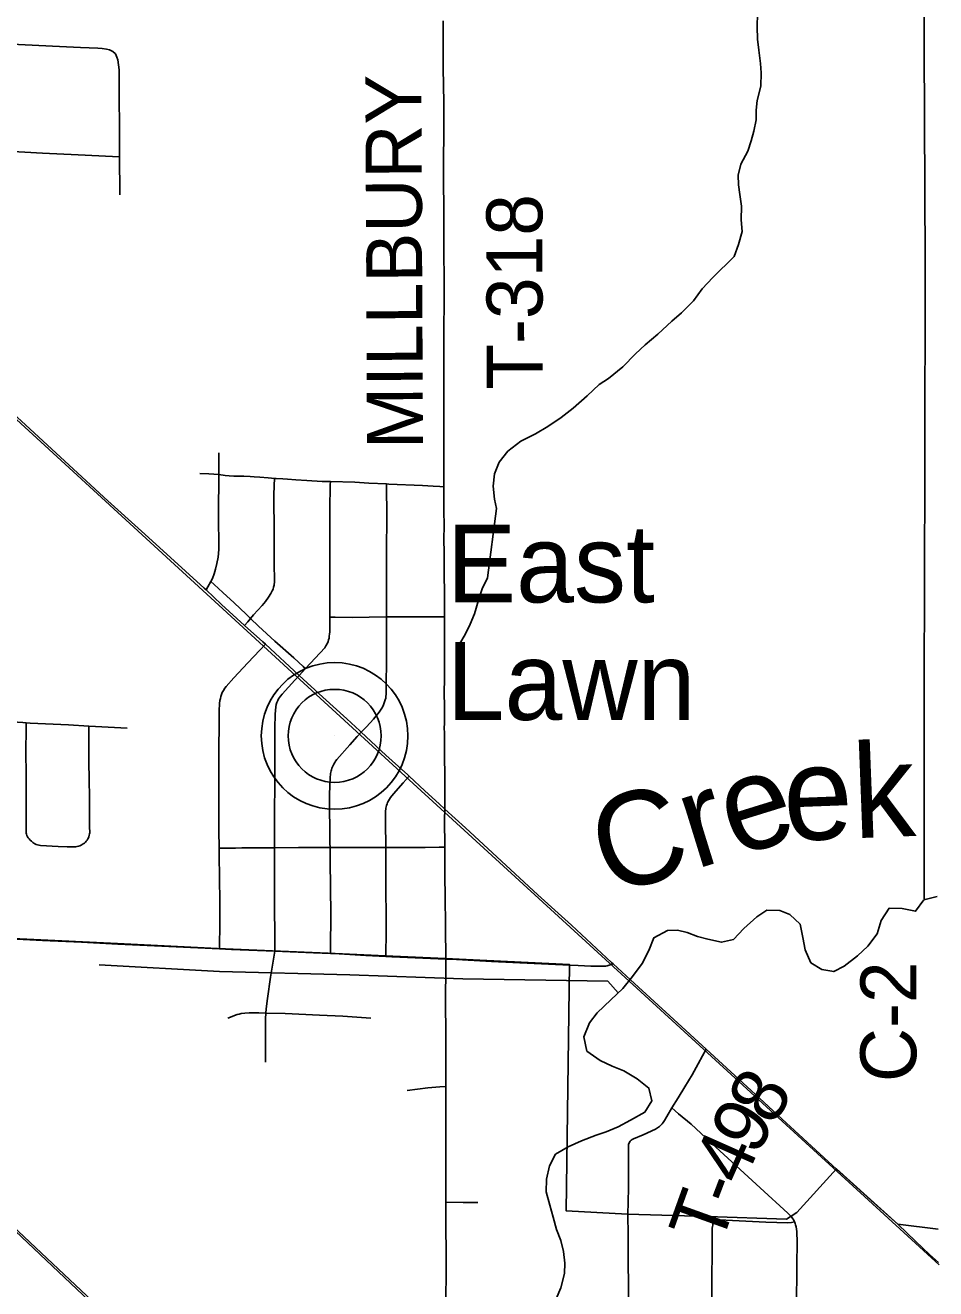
# Model space of a CAD drawing. Extents: x 0 to 34, y 0 to 22.
# Drawn here: x 3.778 to 4.702, y 18.031 to 19.313 of the extents above; entities that cross this region are included whole.
import ezdxf

# ---------------------------------------------------------------- set-up
doc = ezdxf.new("R2010")
doc.units = 0
for name, color, linetype in [('GM_X_City_Street', 7, 'Continuous'), ('GM_X_Corporation', 7, 'Continuous'), ('GM_X_County_Road_Text', 7, 'Continuous'), ('GM_X_Minor_River', 7, 'Continuous'), ('GM_X_Minor_River_Text', 7, 'Continuous'), ('GM_X_Rail_Line', 7, 'Continuous'), ('GM_X_State_Route', 7, 'Continuous'), ('GM_X_Township_Road', 7, 'Continuous'), ('GM_X_Township_Road_Text', 7, 'Continuous'), ('GM_X_Unincorporated', 7, 'Continuous'), ('GM_X_Unincorporated_Location', 7, 'Continuous'), ('GM_X_Unincorporated_Text', 7, 'Continuous')]:
    doc.layers.add(name, color=color, linetype=linetype)

msp = doc.modelspace()

# ---------------------------------------------------------------- linework, layer by layer
at = {"layer": 'GM_X_City_Street'}
for points in [[(4.0224, 18.261), (4.0222, 18.2901), (4.0224, 18.305), (4.0227, 18.3109), (4.023, 18.3154), (4.0242, 18.3259), (4.0274, 18.3474), (4.0316, 18.3737)], [(3.9839, 18.3059), (3.9934, 18.3094), (3.9955, 18.31), (3.9976, 18.3104), (4.0013, 18.3109), (4.0056, 18.3111), (4.0156, 18.3111), (4.0227, 18.3109), (4.0423, 18.3104), (4.0771, 18.3087), (4.1007, 18.3077), (4.129, 18.3058)], [(4.166, 18.2325), (4.1869, 18.235), (4.195, 18.2359), (4.1993, 18.2362), (4.2052, 18.2366)], [(4.2047, 17.9902), (4.2056, 18.043), (4.2054, 18.1191)], [(4.2054, 18.1191), (4.223, 18.1189), (4.2378, 18.1187)], [(4.4761, 17.8564), (4.4762, 17.8627), (4.476, 17.8834), (4.4758, 17.9298), (4.4758, 17.9786), (4.4753, 18.0223), (4.4755, 18.0881), (4.4756, 18.0908), (4.4757, 18.0928), (4.4758, 18.0944), (4.4761, 18.0959), (4.4764, 18.0969), (4.4769, 18.0978), (4.4774, 18.0985), (4.4778, 18.099), (4.4782, 18.0994)], [(4.4782, 18.0994), (4.4788, 18.0998), (4.4797, 18.1003), (4.4808, 18.1007), (4.4817, 18.101), (4.4827, 18.1011), (4.53, 18.0988), (4.5525, 18.0981), (4.556, 18.0985), (4.5592, 18.0993)], [(4.5613, 17.853), (4.5613, 17.859), (4.5615, 17.894), (4.5613, 17.9791), (4.5612, 18.0155), (4.5616, 18.0522), (4.5617, 18.0818), (4.5616, 18.0855), (4.5615, 18.0892), (4.5611, 18.0916), (4.5607, 18.0941), (4.5603, 18.0961), (4.5599, 18.0976), (4.5592, 18.0993)]]:
    msp.add_lwpolyline(points, dxfattribs=at)
at = {"layer": 'GM_X_Corporation'}
msp.add_lwpolyline([(3.7011, 17.8859), (3.7017, 18.3895), (3.872, 18.3816), (3.9736, 18.3766), (4.0293, 18.3741), (4.0857, 18.3716), (4.1442, 18.3689), (4.2049, 18.3663), (4.3308, 18.3601), (4.3274, 18.1103), (4.3898, 18.1068), (4.471, 18.1046), (4.551, 18.1019), (4.5614, 18.1087), (4.6016, 18.153), (4.664, 18.0969), (4.7049, 18.0918)], dxfattribs=at)
at = {"layer": 'GM_X_Minor_River'}
for points in [[(4.6905, 19.9543), (4.6896, 19.826), (4.6912, 19.6693), (4.691, 19.4633), (4.6915, 19.4242), (4.6909, 19.291), (4.6916, 19.0736), (4.6913, 18.8626), (4.6909, 18.6418), (4.6909, 18.427)], [(4.5218, 19.3389), (4.5214, 19.3116), (4.5216, 19.2991), (4.5229, 19.2877), (4.5246, 19.2744), (4.5252, 19.2649), (4.525, 19.2512), (4.5213, 19.2368), (4.5201, 19.227), (4.5203, 19.2171), (4.5178, 19.2058), (4.515, 19.196), (4.5118, 19.1854), (4.5048, 19.1722), (4.502, 19.1609), (4.5022, 19.1514), (4.5036, 19.1415), (4.5053, 19.1297), (4.5051, 19.1157), (4.506, 19.1039), (4.5024, 19.0907), (4.498, 19.0786), (4.4761, 19.0573), (4.4654, 19.0458), (4.4565, 19.0334), (4.4445, 19.0214), (4.4346, 19.0129), (4.4204, 18.9998), (4.4077, 18.989), (4.3977, 18.9797), (4.385, 18.9666), (4.3705, 18.9547), (4.3609, 18.9488), (4.3486, 18.9372), (4.3344, 18.9245), (4.3222, 18.9153), (4.3088, 18.906), (4.2962, 18.8986), (4.2813, 18.8912), (4.2683, 18.8812), (4.2594, 18.87), (4.2547, 18.8579), (4.2534, 18.8454), (4.2547, 18.8325), (4.2568, 18.823), (4.2474, 18.7525), (4.2423, 18.7412), (4.2383, 18.7299), (4.2343, 18.7159), (4.23, 18.7054), (4.2253, 18.6956), (4.2191, 18.6851)], [(4.7038, 18.4291), (4.6905, 18.4259), (4.682, 18.4142), (4.6684, 18.4171), (4.6552, 18.4173), (4.6471, 18.4049), (4.6431, 18.3913), (4.6334, 18.379), (4.623, 18.3689), (4.6096, 18.3585), (4.599, 18.353), (4.5869, 18.3551), (4.5756, 18.3621), (4.5698, 18.3751), (4.5677, 18.3876), (4.5649, 18.401), (4.5545, 18.411), (4.5443, 18.4149), (4.5311, 18.4152), (4.5208, 18.4085), (4.5077, 18.3969), (4.4973, 18.3857), (4.4852, 18.3829), (4.4712, 18.3861), (4.4607, 18.3886), (4.4501, 18.3926), (4.4403, 18.395), (4.4301, 18.3948), (4.4164, 18.3874), (4.4113, 18.3746), (4.4046, 18.3614), (4.3946, 18.3479), (4.3849, 18.3359), (4.3727, 18.3244), (4.3588, 18.3113), (4.3511, 18.3012), (4.3452, 18.2868), (4.3484, 18.2724), (4.3619, 18.2627), (4.3742, 18.2572), (4.3859, 18.2524), (4.3994, 18.2442), (4.4114, 18.2349), (4.4142, 18.222), (4.4072, 18.2103), (4.3927, 18.2022), (4.3801, 18.1956), (4.3679, 18.1905), (4.358, 18.1872), (4.3428, 18.1814), (4.3295, 18.1751), (4.3165, 18.1678), (4.3106, 18.1561), (4.3074, 18.1425), (4.3072, 18.1296), (4.3108, 18.1162), (4.3143, 18.104), (4.3176, 18.0915), (4.3219, 18.0804), (4.3248, 18.069), (4.3261, 18.0572), (4.3256, 18.0469), (4.3219, 18.0322), (4.3172, 18.0209)], [(4.3802, 18.3315), (4.3696, 18.3434), (4.2224, 18.3457), (4.1079, 18.3499), (3.9755, 18.3531), (3.8534, 18.36)]]:
    msp.add_lwpolyline(points, dxfattribs=at)
at = {"layer": 'GM_X_Rail_Line'}
for points in [[(2.1, 20.4531), (2.5585, 20.0312), (3.0884, 19.5461), (3.6994, 18.9771), (4.1763, 18.5403), (4.7059, 18.0556)], [(2.1, 19.6439), (2.1012, 19.6428), (2.4982, 19.2743), (2.9696, 18.8359), (3.3468, 18.4857), (3.702, 18.1547), (3.9505, 17.921), (4.0191, 17.8627), (4.0357, 17.8486), (4.0945, 17.8067), (4.1695, 17.7587), (4.2566, 17.7148), (4.3444, 17.681), (4.4559, 17.6499), (4.5498, 17.6344), (4.6383, 17.6263), (4.7029, 17.6237), (4.7039, 17.6237)], [(2.1, 19.64), (2.4967, 19.2714), (2.9674, 18.8343), (3.3458, 18.483), (3.6997, 18.1544), (3.9489, 17.9193), (4.0176, 17.861), (4.0342, 17.8468), (4.0931, 17.8048), (4.1683, 17.7567), (4.2556, 17.7127), (4.3436, 17.6788), (4.4554, 17.6477), (4.5495, 17.6321), (4.6381, 17.624), (4.7029, 17.6214), (4.7039, 17.6214)]]:
    msp.add_lwpolyline(points, dxfattribs=at)
at = {"layer": 'GM_X_State_Route'}
for points in [[(3.9619, 18.7402), (3.9599, 18.7422), (3.9221, 18.7764), (3.8965, 18.8), (3.8623, 18.8308), (3.8055, 18.8829), (3.7786, 18.9078), (3.758, 18.9268), (3.7357, 18.9476), (3.7211, 18.9611), (3.7048, 18.9762), (3.7015, 18.9792)], [(3.7015, 18.9792), (3.7048, 18.9762), (3.7211, 18.9611), (3.7357, 18.9476), (3.758, 18.9268), (3.7786, 18.9078), (3.8055, 18.8829), (3.8623, 18.8308), (3.8965, 18.8), (3.9221, 18.7764), (3.9599, 18.7422), (3.9619, 18.7402)], [(4.6019, 18.1525), (4.5466, 18.2034), (4.5237, 18.2245), (4.4694, 18.2742), (4.4365, 18.3043), (4.3926, 18.3447), (4.375, 18.3609), (4.3734, 18.3624), (4.3328, 18.4001), (4.3194, 18.4122), (4.2986, 18.4309), (4.2617, 18.4652), (4.2251, 18.499), (4.2041, 18.5179), (4.1985, 18.5231), (4.1839, 18.5366), (4.1681, 18.5513), (4.1666, 18.5527), (4.1444, 18.5727), (4.1194, 18.5958), (4.1179, 18.5972), (4.1047, 18.6094), (4.0804, 18.6316), (4.0565, 18.6535), (4.0221, 18.6852), (4.0195, 18.6876), (4.0009, 18.7042), (3.9775, 18.7255), (3.9619, 18.7402)], [(3.9619, 18.7402), (3.9775, 18.7255), (4.0009, 18.7042), (4.0195, 18.6876), (4.0221, 18.6852), (4.0565, 18.6535), (4.0804, 18.6316), (4.1047, 18.6094), (4.1179, 18.5972), (4.1194, 18.5958), (4.1444, 18.5727), (4.1666, 18.5527), (4.1681, 18.5513), (4.1839, 18.5366), (4.1985, 18.5231), (4.2041, 18.5179), (4.2251, 18.499), (4.2617, 18.4652), (4.2986, 18.4309), (4.3194, 18.4122), (4.3328, 18.4001), (4.3734, 18.3624), (4.375, 18.3609), (4.3926, 18.3447), (4.4365, 18.3043), (4.4694, 18.2742), (4.5237, 18.2245), (4.5466, 18.2034), (4.6019, 18.1525)], [(4.6642, 18.0963), (4.6399, 18.1181), (4.6113, 18.1442), (4.6019, 18.1525)], [(4.6019, 18.1525), (4.6113, 18.1442), (4.6399, 18.1181), (4.6642, 18.0963)], [(4.7052, 18.0579), (4.6963, 18.0659), (4.6818, 18.0796), (4.6642, 18.0963)], [(4.6642, 18.0963), (4.6818, 18.0796), (4.6963, 18.0659), (4.7052, 18.0579)]]:
    msp.add_lwpolyline(points, dxfattribs=at)
at = {"layer": 'GM_X_Township_Road'}
msp.add_line((4.0565, 18.6535), (4.0629, 18.6605), dxfattribs=at)
for points in [[(4.2033, 18.845), (4.2033, 18.8574), (4.2033, 18.8735), (4.2034, 18.8984), (4.2033, 18.9164), (4.2033, 18.9419), (4.2032, 18.9805), (4.2033, 19.0016), (4.2036, 19.0357), (4.2035, 19.0487), (4.2032, 19.0892), (4.2031, 19.1039), (4.2032, 19.1282), (4.2029, 19.1537), (4.203, 19.1611), (4.203, 19.1817), (4.2031, 19.1984), (4.2032, 19.2146), (4.2032, 19.2345), (4.2026, 19.27), (4.2026, 19.2818), (4.2027, 19.3051), (4.2026, 19.3175)], [(3.7001, 19.2969), (3.7085, 19.2966), (3.716, 19.2964), (3.806, 19.292), (3.8346, 19.2906), (3.852, 19.2898), (3.8565, 19.2895), (3.8608, 19.289), (3.8639, 19.2881), (3.8674, 19.2866), (3.87, 19.2842)], [(3.8741, 19.1795), (3.874, 19.2138), (3.8737, 19.2362), (3.8738, 19.2549), (3.8736, 19.268), (3.8732, 19.273), (3.8723, 19.278), (3.8715, 19.2806), (3.87, 19.2842)], [(3.7007, 19.1883), (3.7089, 19.188), (3.7138, 19.1878), (3.7275, 19.1872), (3.7599, 19.1854), (3.7959, 19.1835), (3.832, 19.1818), (3.8668, 19.1799), (3.8741, 19.1795)], [(3.8743, 19.141), (3.8743, 19.1522), (3.8741, 19.1703), (3.8741, 19.1795)], [(3.9748, 18.8572), (3.9749, 18.8652), (3.9748, 18.8793)], [(3.9556, 18.8585), (3.9648, 18.858), (3.9748, 18.8572)], [(3.9666, 18.7488), (3.9683, 18.752), (3.9701, 18.7566), (3.9715, 18.7614), (3.973, 18.7669), (3.9741, 18.7734), (3.9745, 18.7771), (3.9748, 18.7815), (3.9748, 18.7908), (3.9746, 18.8078), (3.9744, 18.8171), (3.9748, 18.8572)], [(3.9748, 18.8572), (3.9813, 18.8565), (3.9852, 18.8559), (3.9902, 18.8558), (4.0003, 18.8556), (4.0068, 18.8552), (4.0107, 18.8551), (4.0166, 18.8547), (4.0251, 18.8539), (4.0282, 18.8536), (4.0313, 18.8534)], [(4.0071, 18.7113), (4.0102, 18.7149), (4.019, 18.7246), (4.0222, 18.7285), (4.0253, 18.733), (4.0276, 18.7366), (4.0291, 18.7393), (4.0299, 18.7411), (4.0305, 18.7429), (4.031, 18.745), (4.0315, 18.7487), (4.0315, 18.7521), (4.0313, 18.7553), (4.0312, 18.7613), (4.0311, 18.7731), (4.0312, 18.7766), (4.0312, 18.782), (4.0312, 18.7863), (4.031, 18.7969), (4.031, 18.8099), (4.0308, 18.8238), (4.0307, 18.8286), (4.0307, 18.8365), (4.031, 18.8463), (4.0313, 18.8534)], [(4.0313, 18.8534), (4.0332, 18.8532), (4.0398, 18.8528), (4.0446, 18.8526), (4.0531, 18.8521), (4.0642, 18.8514), (4.0796, 18.8504), (4.0881, 18.8502)], [(4.0874, 18.7126), (4.0876, 18.7608), (4.0875, 18.7795), (4.0876, 18.8217), (4.088, 18.8468), (4.0881, 18.8502)], [(4.0881, 18.8502), (4.113, 18.8496), (4.1272, 18.8487), (4.1449, 18.8478)], [(4.1449, 18.8478), (4.1473, 18.8477), (4.1815, 18.8461), (4.1925, 18.8456), (4.1993, 18.8453), (4.2033, 18.845)], [(4.1449, 18.7128), (4.1449, 18.7191), (4.1451, 18.778), (4.1453, 18.8164), (4.145, 18.8444), (4.1449, 18.8478)], [(4.2039, 18.7128), (4.2039, 18.7359), (4.2038, 18.7383), (4.2036, 18.755), (4.2035, 18.7587), (4.2036, 18.7779), (4.2034, 18.7916), (4.2035, 18.8053), (4.2034, 18.8207), (4.2033, 18.845)], [(3.9619, 18.7402), (3.9637, 18.7435), (3.9666, 18.7488)], [(3.9666, 18.7488), (3.97, 18.7457), (3.9791, 18.7376), (3.9905, 18.727), (4.0027, 18.7155), (4.0071, 18.7113)], [(4.0009, 18.7042), (4.0043, 18.708), (4.0071, 18.7113)], [(4.0071, 18.7113), (4.0153, 18.7035), (4.0317, 18.6883), (4.0509, 18.6715), (4.0605, 18.6627), (4.0629, 18.6605)], [(4.0629, 18.6605), (4.0824, 18.6816), (4.0836, 18.6834), (4.085, 18.6861), (4.0857, 18.6879), (4.0863, 18.6896), (4.0867, 18.6912), (4.087, 18.693), (4.0873, 18.6956), (4.0874, 18.6975), (4.0874, 18.6994), (4.0874, 18.7126)], [(4.0874, 18.7126), (4.0928, 18.7125), (4.1109, 18.7123), (4.1276, 18.7127), (4.1449, 18.7128)], [(4.1194, 18.5958), (4.1249, 18.6013), (4.1317, 18.6093), (4.1376, 18.6164), (4.139, 18.6184), (4.1403, 18.6204), (4.1416, 18.6227), (4.1424, 18.6246), (4.1431, 18.6267), (4.1438, 18.6287), (4.1443, 18.6304), (4.1445, 18.6324), (4.1447, 18.6342), (4.1447, 18.6368), (4.1449, 18.6753), (4.1449, 18.7128)], [(4.1449, 18.7128), (4.1469, 18.7128), (4.1749, 18.7131), (4.1971, 18.7129), (4.2039, 18.7128)], [(4.2041, 18.5179), (4.2042, 18.5235), (4.2041, 18.5295), (4.2044, 18.5507), (4.204, 18.5725), (4.2039, 18.5936), (4.2038, 18.5955), (4.2037, 18.5998), (4.2038, 18.6054), (4.2038, 18.6172), (4.2038, 18.6246), (4.2037, 18.6333), (4.2037, 18.6377), (4.2039, 18.6488), (4.2039, 18.6569), (4.204, 18.67), (4.204, 18.6737), (4.2039, 18.6806), (4.204, 18.6892), (4.204, 18.6998), (4.2039, 18.7054), (4.2039, 18.7066), (4.2039, 18.7128)], [(3.9751, 18.4783), (3.9749, 18.4962), (3.9749, 18.5206), (3.9749, 18.5328), (3.975, 18.5633), (3.9753, 18.6197), (3.9754, 18.623), (3.9756, 18.625), (3.976, 18.628), (3.9765, 18.6302), (3.977, 18.6323), (3.9776, 18.6341), (3.9784, 18.6361), (3.9795, 18.6382), (3.9809, 18.6405), (3.9823, 18.6424), (3.99, 18.651), (4.0044, 18.6664), (4.0164, 18.6791), (4.0221, 18.6852)], [(4.0315, 18.4787), (4.0315, 18.5174), (4.0318, 18.5404), (4.0318, 18.6), (4.0322, 18.6143), (4.0328, 18.6218), (4.0332, 18.624), (4.0339, 18.6261), (4.0347, 18.628), (4.0355, 18.6297), (4.0365, 18.6312), (4.0375, 18.6324), (4.0391, 18.6345), (4.0521, 18.6488), (4.0565, 18.6535)], [(3.7426, 18.6104), (3.7652, 18.6066), (3.7759, 18.6056), (3.7794, 18.6054)], [(3.7794, 18.6054), (3.7793, 18.5969), (3.7791, 18.5786), (3.7792, 18.5503), (3.7792, 18.5202), (3.7793, 18.4947), (3.7794, 18.4936), (3.7796, 18.4925), (3.7801, 18.4911), (3.7806, 18.4899), (3.7814, 18.4887), (3.7823, 18.4876), (3.7835, 18.4863), (3.7847, 18.4852), (3.786, 18.4841), (3.7872, 18.4833), (3.7883, 18.4827), (3.7895, 18.4821), (3.7909, 18.4816), (3.7925, 18.4812), (3.7939, 18.4809), (3.8119, 18.4801), (3.8209, 18.4797), (3.8295, 18.4795), (3.8309, 18.4798), (3.8325, 18.4802), (3.8338, 18.4807), (3.835, 18.4812), (3.8363, 18.4819), (3.8373, 18.4826), (3.8385, 18.4834), (3.8394, 18.4843), (3.8404, 18.4855), (3.8412, 18.4864), (3.8419, 18.4876), (3.8425, 18.4888), (3.8429, 18.4898), (3.8434, 18.4914), (3.8436, 18.4927), (3.8438, 18.4938), (3.8437, 18.5004), (3.8435, 18.5142), (3.8436, 18.5314), (3.8433, 18.5463), (3.843, 18.5674), (3.843, 18.5947), (3.843, 18.6021)], [(3.7794, 18.6054), (3.7834, 18.6051), (3.8224, 18.6033), (3.843, 18.6021), (3.8497, 18.6017), (3.8818, 18.6001)], [(4.0878, 18.479), (4.0877, 18.4834), (4.0873, 18.5324), (4.0879, 18.5508), (4.0881, 18.5527), (4.0882, 18.554), (4.0885, 18.5553), (4.0888, 18.5566), (4.0892, 18.5579), (4.0897, 18.5593), (4.0903, 18.5607), (4.0909, 18.562), (4.0916, 18.5634), (4.0925, 18.5651), (4.0934, 18.5666), (4.0946, 18.5682), (4.1078, 18.5832), (4.1152, 18.5915), (4.1194, 18.5958)], [(4.1444, 18.479), (4.1441, 18.505), (4.1442, 18.515), (4.1445, 18.5187), (4.1447, 18.5203), (4.1451, 18.5217), (4.1456, 18.5232), (4.1462, 18.5247), (4.147, 18.5264), (4.148, 18.5281), (4.149, 18.5295), (4.1521, 18.5334), (4.1621, 18.5445), (4.1681, 18.5513)], [(4.2042, 18.4793), (4.204, 18.5073), (4.2041, 18.5179)], [(3.9751, 18.4783), (3.9801, 18.4783), (3.9919, 18.4783), (3.9981, 18.4786), (4.0203, 18.4786), (4.0315, 18.4787)], [(3.9754, 18.3762), (3.9755, 18.3832), (3.9758, 18.3962), (3.9759, 18.4273), (3.9756, 18.4447), (3.9751, 18.4746), (3.9751, 18.4783)], [(4.0316, 18.3737), (4.0316, 18.3783), (4.0314, 18.4298), (4.0315, 18.4787)], [(4.0315, 18.4787), (4.0558, 18.4788), (4.0707, 18.4789), (4.0825, 18.479), (4.0878, 18.479)], [(4.0878, 18.479), (4.0912, 18.4791), (4.1427, 18.479), (4.1444, 18.479)], [(4.0883, 18.3713), (4.0883, 18.3767), (4.0884, 18.4108), (4.0878, 18.4654), (4.0878, 18.479)], [(4.1444, 18.479), (4.1843, 18.4791), (4.1986, 18.4793), (4.2042, 18.4793)], [(4.1444, 18.3683), (4.1445, 18.3742), (4.1447, 18.3891), (4.1446, 18.3959), (4.1445, 18.4498), (4.1444, 18.4709), (4.1444, 18.479)], [(4.2051, 18.3658), (4.2048, 18.3985), (4.2048, 18.4072), (4.2045, 18.4215), (4.2045, 18.4296), (4.2046, 18.4345), (4.2044, 18.4445), (4.2042, 18.4633), (4.2043, 18.4706), (4.2042, 18.4793)], [(3.7022, 18.3893), (3.7431, 18.3872), (3.7636, 18.3862), (3.7959, 18.3847), (3.8356, 18.3829), (3.8723, 18.381), (3.9095, 18.3791), (3.9754, 18.3762)], [(3.9754, 18.3762), (3.9878, 18.3756), (4.0316, 18.3737)], [(4.0316, 18.3737), (4.0708, 18.372), (4.0883, 18.3713)], [(4.0883, 18.3713), (4.0969, 18.3709), (4.1242, 18.3694), (4.1444, 18.3683)], [(4.1444, 18.3683), (4.1503, 18.368), (4.1664, 18.3674), (4.2051, 18.3658)], [(4.2052, 18.2366), (4.2051, 18.2667), (4.2051, 18.2922), (4.205, 18.3196), (4.2051, 18.3613), (4.2051, 18.3658)], [(4.2051, 18.3658), (4.2161, 18.3653), (4.2515, 18.3634), (4.331, 18.3596)], [(4.331, 18.3596), (4.3396, 18.3591), (4.3525, 18.3587), (4.3643, 18.3584), (4.3663, 18.3585), (4.3675, 18.3586), (4.3689, 18.359), (4.375, 18.3609)], [(4.4347, 18.2147), (4.4411, 18.2249), (4.4479, 18.2361), (4.4552, 18.2482), (4.4615, 18.2595), (4.4658, 18.2675), (4.4694, 18.2742)], [(4.2054, 18.1191), (4.2053, 18.1685), (4.2052, 18.2021), (4.2052, 18.2338), (4.2052, 18.2366)], [(4.3901, 18.1062), (4.3905, 18.1332), (4.3906, 18.1745), (4.3906, 18.1761), (4.3908, 18.1779), (4.3912, 18.1791), (4.3916, 18.1801), (4.3924, 18.1811), (4.3934, 18.182), (4.3945, 18.1828), (4.3959, 18.1835), (4.4054, 18.1876), (4.4182, 18.1932), (4.4202, 18.1944), (4.4221, 18.1959), (4.4236, 18.1972), (4.4249, 18.1987), (4.426, 18.2001), (4.4272, 18.202), (4.4295, 18.2059), (4.4347, 18.2147)], [(4.4347, 18.2147), (4.4414, 18.2089), (4.4543, 18.1981), (4.4793, 18.175), (4.5242, 18.1337), (4.5524, 18.1079), (4.556, 18.1042), (4.5574, 18.1023), (4.5584, 18.1009), (4.5592, 18.0993)], [(4.3909, 17.8591), (4.3908, 17.8662), (4.3908, 17.8994), (4.3905, 17.9465), (4.3906, 17.9913), (4.3905, 18.0377), (4.3904, 18.0556), (4.3903, 18.0859), (4.3901, 18.1062)]]:
    msp.add_lwpolyline(points, dxfattribs=at)
at = {"layer": 'GM_X_Unincorporated'}
for radius in [0.0744, 0.0472]:
    msp.add_circle((4.0924, 18.5922), radius, dxfattribs=at)
at = {"layer": 'GM_X_Unincorporated_Location'}
msp.add_line((4.0924, 18.5922), (4.0924, 18.5922), dxfattribs=at)

# ---------------------------------------------------------------- texts
at = {"layer": 'GM_X_County_Road_Text'}
msp.add_text('C-2', height=0.05682, rotation=89.907, dxfattribs=at).set_placement((4.6827, 18.2409))
at = {"layer": 'GM_X_Minor_River_Text'}
for s, rotation, p in [('ek', 2.1966, (4.5492, 18.4856)), ('Cre', 17.1996, (4.3708, 18.4296))]:
    msp.add_text(s, height=0.09476, rotation=rotation, dxfattribs=at).set_placement(p)
at = {"layer": 'GM_X_Township_Road_Text'}
for s, height, rotation, p in [('MILLBURY', 0.05682, 90.2636, (4.1821, 18.8832)), ('T-318', 0.05682, 90.1295, (4.3036, 18.9434)), ('8', 0.0568, 59.6752, (4.5374, 18.1951)), ('9', 0.0568, 59.6012, (4.5197, 18.1648)), ('4', 0.0568, 66.0423, (4.5063, 18.1343)), ('-', 0.0568, 69.1945, (4.4983, 18.1133)), ('T', 0.0568, 70.2029, (4.484, 18.0735))]:
    msp.add_text(s, height=height, rotation=rotation, dxfattribs=at).set_placement(p)
at = {"layer": 'GM_X_Unincorporated_Text'}
for s, p in [('East', (4.2061, 18.7276)), ('Lawn', (4.2061, 18.6084))]:
    msp.add_text(s, height=0.07898, rotation=0, dxfattribs=at).set_placement(p)

doc.saveas('drawing.dxf')
